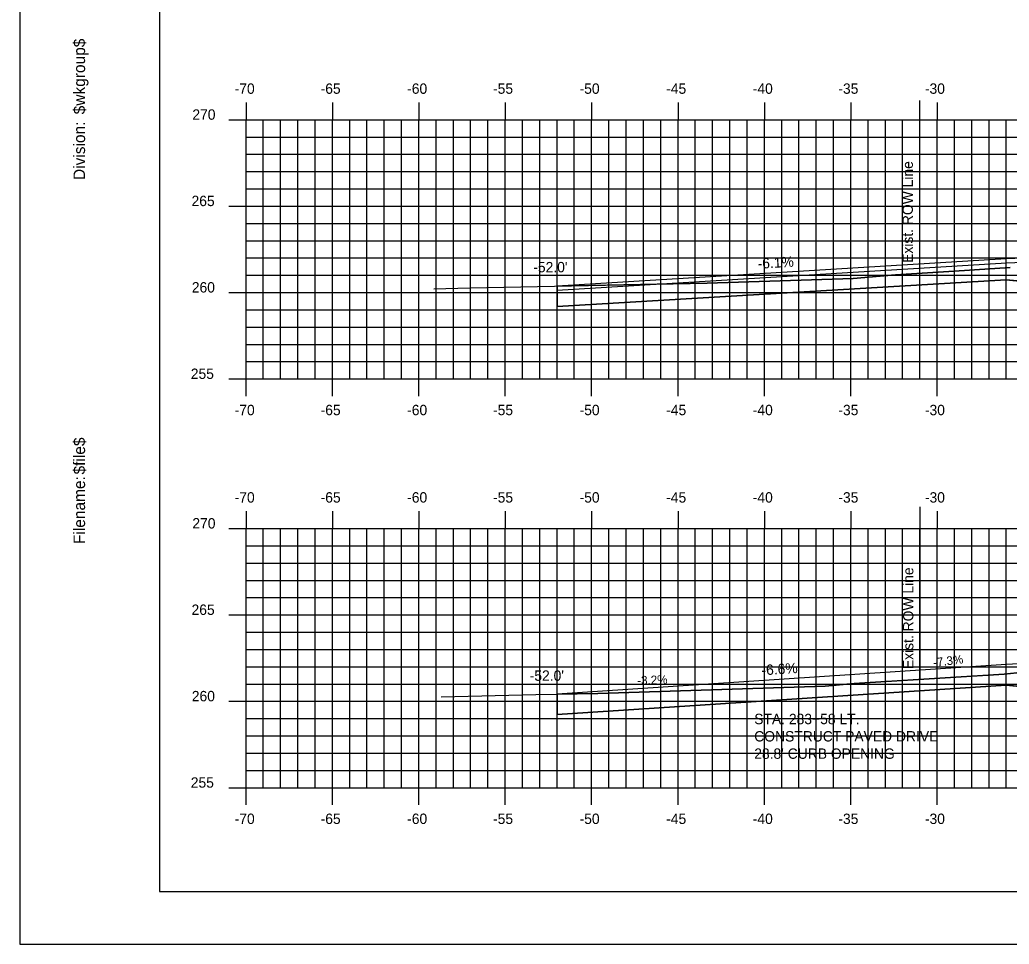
# Model space of a CAD drawing. Extents: x 856235 to 856405, y 366268 to 366378.
# Drawn here: x 856234.7 to 856291.9, y 366268.2 to 366321.7 of the extents above; entities that cross this region are included whole.
import ezdxf

# ---------------------------------------------------------------- set-up
doc = ezdxf.new("R2010")
doc.units = 0
for name, color, linetype in [('ANNOTATION', 7, 'Continuous'), ('BORDER', 7, 'Continuous'), ('D_Roadway_Drive_Gravel_LT', 7, 'Continuous'), ('D_Roadway_Drive_SubGrade', 7, 'Continuous'), ('D_Text_Monospaced', 7, 'Continuous'), ('D_Text_Standard', 7, 'Continuous'), ('E_ROW_Line', 7, 'Continuous'), ('H_V ANNOTATION', 7, 'Continuous'), ('JUNK COM EXC', 7, 'Continuous'), ('MAJOR', 7, 'Continuous'), ('MINOR', 7, 'Continuous'), ('PLOT BOUNDARY', 7, 'Continuous'), ('S_Roadway_Centerline', 7, 'Continuous')]:
    doc.layers.add(name, color=color, linetype=linetype)

msp = doc.modelspace()

# ---------------------------------------------------------------- linework, layer by layer
at = {"layer": 'BORDER'}
for p, q in [((856242.781, 366376.236), (856242.781, 366271.236)), ((856242.781, 366271.236), (856402.781, 366271.236))]:
    msp.add_line(p, q, dxfattribs=at)
at = {"layer": 'D_Roadway_Drive_Gravel_LT'}
for p, q in [((856291.781, 366307.834), (856265.781, 366306.26)), ((856291.796, 366307.584), (856265.781, 366306.009)), ((856297.781, 366308.074), (856291.781, 366307.834)), ((856297.791, 366307.824), (856291.791, 366307.584)), ((856291.781, 366306.632), (856265.781, 366305.093)), ((856291.781, 366284.374), (856265.781, 366282.647)), ((856297.781, 366284.614), (856291.781, 366284.374)), ((856291.781, 366283.178), (856265.781, 366281.48))]:
    msp.add_line(p, q, dxfattribs=at)
at = {"layer": 'D_Roadway_Drive_SubGrade'}
for p, q in [((856301.781, 366305.64), (856291.781, 366306.632)), ((856265.781, 366306.26), (856265.781, 366305.093)), ((856301.781, 366282.181), (856291.781, 366283.178)), ((856265.781, 366282.647), (856265.781, 366281.48))]:
    msp.add_line(p, q, dxfattribs=at)
at = {"layer": 'E_ROW_Line'}
for p, q in [((856286.774, 366307.01), (856286.774, 366317.01)), ((856286.803, 366283.499), (856286.803, 366293.499))]:
    msp.add_line(p, q, dxfattribs=at)
at = {"layer": 'JUNK COM EXC'}
for points in [[(856291.997, 366307.346), (856288.766, 366307.134), (856285.366, 366306.922), (856282.92, 366306.703), (856278.69, 366306.569), (856274.46, 366306.436), (856265.781, 366306.26), (856265.781, 366305.093), (856291.781, 366306.632), (856301.781, 366305.64)], [(856293.851, 366284.031), (856291.653, 366283.81), (856282.975, 366283.26), (856281.3, 366283.11), (856274.723, 366282.902), (856268.146, 366282.695), (856265.781, 366282.647), (856265.781, 366281.48), (856291.781, 366283.178), (856301.781, 366282.181)]]:
    msp.add_lwpolyline(points, dxfattribs=at)
at = {"layer": 'MAJOR'}
for p, q in [((856247.781, 366316.895), (856247.781, 366315.893)), ((856252.781, 366316.895), (856252.781, 366315.893)), ((856257.781, 366316.895), (856257.781, 366315.893)), ((856262.781, 366316.895), (856262.781, 366315.893)), ((856267.781, 366316.895), (856267.781, 366315.893)), ((856272.781, 366316.895), (856272.781, 366315.893)), ((856277.781, 366316.895), (856277.781, 366315.893)), ((856282.781, 366316.895), (856282.781, 366315.893)), ((856287.781, 366316.895), (856287.781, 366315.893)), ((856246.779, 366315.893), (856247.781, 366315.893)), ((856247.781, 366315.893), (856387.781, 366315.893)), ((856247.781, 366300.893), (856247.781, 366315.893)), ((856247.781, 366300.893), (856247.781, 366315.893)), ((856247.781, 366315.893), (856387.781, 366315.893)), ((856252.781, 366300.893), (856252.781, 366315.893)), ((856257.781, 366300.893), (856257.781, 366315.893)), ((856262.781, 366300.893), (856262.781, 366315.893)), ((856267.781, 366300.893), (856267.781, 366315.893)), ((856272.781, 366300.893), (856272.781, 366315.893)), ((856277.781, 366300.893), (856277.781, 366315.893)), ((856282.781, 366300.893), (856282.781, 366315.893)), ((856287.781, 366300.893), (856287.781, 366315.893)), ((856246.779, 366310.893), (856247.781, 366310.893)), ((856247.781, 366310.893), (856387.781, 366310.893)), ((856246.779, 366305.893), (856247.781, 366305.893)), ((856247.781, 366305.893), (856387.781, 366305.893)), ((856246.779, 366300.893), (856247.781, 366300.893)), ((856247.781, 366300.893), (856387.781, 366300.893)), ((856247.781, 366300.893), (856387.781, 366300.893)), ((856247.781, 366299.891), (856247.781, 366300.893)), ((856252.781, 366299.891), (856252.781, 366300.893)), ((856257.781, 366299.891), (856257.781, 366300.893)), ((856262.781, 366299.891), (856262.781, 366300.893)), ((856267.781, 366299.891), (856267.781, 366300.893)), ((856272.781, 366299.891), (856272.781, 366300.893)), ((856277.781, 366299.891), (856277.781, 366300.893)), ((856282.781, 366299.891), (856282.781, 366300.893)), ((856287.781, 366299.891), (856287.781, 366300.893)), ((856247.781, 366293.238), (856247.781, 366292.236)), ((856252.781, 366293.238), (856252.781, 366292.236)), ((856257.781, 366293.238), (856257.781, 366292.236)), ((856262.781, 366293.238), (856262.781, 366292.236)), ((856267.781, 366293.238), (856267.781, 366292.236)), ((856272.781, 366293.238), (856272.781, 366292.236)), ((856277.781, 366293.238), (856277.781, 366292.236)), ((856282.781, 366293.238), (856282.781, 366292.236)), ((856287.781, 366293.238), (856287.781, 366292.236)), ((856246.779, 366292.236), (856247.781, 366292.236)), ((856247.781, 366292.236), (856387.781, 366292.236)), ((856247.781, 366277.236), (856247.781, 366292.236)), ((856247.781, 366277.236), (856247.781, 366292.236)), ((856247.781, 366292.236), (856387.781, 366292.236)), ((856252.781, 366277.236), (856252.781, 366292.236)), ((856257.781, 366277.236), (856257.781, 366292.236)), ((856262.781, 366277.236), (856262.781, 366292.236)), ((856267.781, 366277.236), (856267.781, 366292.236)), ((856272.781, 366277.236), (856272.781, 366292.236)), ((856277.781, 366277.236), (856277.781, 366292.236)), ((856282.781, 366277.236), (856282.781, 366292.236)), ((856287.781, 366277.236), (856287.781, 366292.236)), ((856246.779, 366287.236), (856247.781, 366287.236)), ((856247.781, 366287.236), (856387.781, 366287.236)), ((856246.779, 366282.236), (856247.781, 366282.236)), ((856247.781, 366282.236), (856387.781, 366282.236)), ((856246.779, 366277.236), (856247.781, 366277.236)), ((856247.781, 366277.236), (856387.781, 366277.236)), ((856247.781, 366277.236), (856387.781, 366277.236)), ((856247.781, 366276.234), (856247.781, 366277.236)), ((856252.781, 366276.234), (856252.781, 366277.236)), ((856257.781, 366276.234), (856257.781, 366277.236)), ((856262.781, 366276.234), (856262.781, 366277.236)), ((856267.781, 366276.234), (856267.781, 366277.236)), ((856272.781, 366276.234), (856272.781, 366277.236)), ((856277.781, 366276.234), (856277.781, 366277.236)), ((856282.781, 366276.234), (856282.781, 366277.236)), ((856287.781, 366276.234), (856287.781, 366277.236))]:
    msp.add_line(p, q, dxfattribs=at)
at = {"layer": 'MINOR'}
for p, q in [((856248.781, 366300.893), (856248.781, 366315.893)), ((856249.781, 366300.893), (856249.781, 366315.893)), ((856250.781, 366300.893), (856250.781, 366315.893)), ((856251.781, 366300.893), (856251.781, 366315.893)), ((856253.781, 366300.893), (856253.781, 366315.893)), ((856254.781, 366300.893), (856254.781, 366315.893)), ((856255.781, 366300.893), (856255.781, 366315.893)), ((856256.781, 366300.893), (856256.781, 366315.893)), ((856258.781, 366300.893), (856258.781, 366315.893)), ((856259.781, 366300.893), (856259.781, 366315.893)), ((856260.781, 366300.893), (856260.781, 366315.893)), ((856261.781, 366300.893), (856261.781, 366315.893)), ((856263.781, 366300.893), (856263.781, 366315.893)), ((856264.781, 366300.893), (856264.781, 366315.893)), ((856265.781, 366300.893), (856265.781, 366315.893)), ((856266.781, 366300.893), (856266.781, 366315.893)), ((856268.781, 366300.893), (856268.781, 366315.893)), ((856269.781, 366300.893), (856269.781, 366315.893)), ((856270.781, 366300.893), (856270.781, 366315.893)), ((856271.781, 366300.893), (856271.781, 366315.893)), ((856273.781, 366300.893), (856273.781, 366315.893)), ((856274.781, 366300.893), (856274.781, 366315.893)), ((856275.781, 366300.893), (856275.781, 366315.893)), ((856276.781, 366300.893), (856276.781, 366315.893)), ((856278.781, 366300.893), (856278.781, 366315.893)), ((856279.781, 366300.893), (856279.781, 366315.893)), ((856280.781, 366300.893), (856280.781, 366315.893)), ((856281.781, 366300.893), (856281.781, 366315.893)), ((856283.781, 366300.893), (856283.781, 366315.893)), ((856284.781, 366300.893), (856284.781, 366315.893)), ((856285.781, 366300.893), (856285.781, 366315.893)), ((856286.781, 366300.893), (856286.781, 366315.893)), ((856288.781, 366300.893), (856288.781, 366315.893)), ((856289.781, 366300.893), (856289.781, 366315.893)), ((856290.781, 366300.893), (856290.781, 366315.893)), ((856291.781, 366300.893), (856291.781, 366315.893)), ((856247.781, 366314.893), (856387.781, 366314.893)), ((856247.781, 366314.893), (856248.783, 366314.893)), ((856247.781, 366313.893), (856387.781, 366313.893)), ((856247.781, 366313.893), (856248.783, 366313.893)), ((856247.781, 366312.893), (856387.781, 366312.893)), ((856247.781, 366312.893), (856248.783, 366312.893)), ((856247.781, 366311.893), (856387.781, 366311.893)), ((856247.781, 366311.893), (856248.783, 366311.893)), ((856247.781, 366309.893), (856387.781, 366309.893)), ((856247.781, 366309.893), (856248.783, 366309.893)), ((856247.781, 366308.893), (856387.781, 366308.893)), ((856247.781, 366308.893), (856248.783, 366308.893)), ((856247.781, 366307.893), (856387.781, 366307.893)), ((856247.781, 366307.893), (856248.783, 366307.893)), ((856247.781, 366306.893), (856387.781, 366306.893)), ((856247.781, 366306.893), (856248.783, 366306.893)), ((856247.781, 366304.893), (856387.781, 366304.893)), ((856247.781, 366304.893), (856248.783, 366304.893)), ((856247.781, 366303.893), (856387.781, 366303.893)), ((856247.781, 366303.893), (856248.783, 366303.893)), ((856247.781, 366302.893), (856387.781, 366302.893)), ((856247.781, 366302.893), (856248.783, 366302.893)), ((856247.781, 366301.893), (856387.781, 366301.893)), ((856247.781, 366301.893), (856248.783, 366301.893)), ((856248.781, 366277.236), (856248.781, 366292.236)), ((856249.781, 366277.236), (856249.781, 366292.236)), ((856250.781, 366277.236), (856250.781, 366292.236)), ((856251.781, 366277.236), (856251.781, 366292.236)), ((856253.781, 366277.236), (856253.781, 366292.236)), ((856254.781, 366277.236), (856254.781, 366292.236)), ((856255.781, 366277.236), (856255.781, 366292.236)), ((856256.781, 366277.236), (856256.781, 366292.236)), ((856258.781, 366277.236), (856258.781, 366292.236)), ((856259.781, 366277.236), (856259.781, 366292.236)), ((856260.781, 366277.236), (856260.781, 366292.236)), ((856261.781, 366277.236), (856261.781, 366292.236)), ((856263.781, 366277.236), (856263.781, 366292.236)), ((856264.781, 366277.236), (856264.781, 366292.236)), ((856265.781, 366277.236), (856265.781, 366292.236)), ((856266.781, 366277.236), (856266.781, 366292.236)), ((856268.781, 366277.236), (856268.781, 366292.236)), ((856269.781, 366277.236), (856269.781, 366292.236)), ((856270.781, 366277.236), (856270.781, 366292.236)), ((856271.781, 366277.236), (856271.781, 366292.236)), ((856273.781, 366277.236), (856273.781, 366292.236)), ((856274.781, 366277.236), (856274.781, 366292.236)), ((856275.781, 366277.236), (856275.781, 366292.236)), ((856276.781, 366277.236), (856276.781, 366292.236)), ((856278.781, 366277.236), (856278.781, 366292.236)), ((856279.781, 366277.236), (856279.781, 366292.236)), ((856280.781, 366277.236), (856280.781, 366292.236)), ((856281.781, 366277.236), (856281.781, 366292.236)), ((856283.781, 366277.236), (856283.781, 366292.236)), ((856284.781, 366277.236), (856284.781, 366292.236)), ((856285.781, 366277.236), (856285.781, 366292.236)), ((856286.781, 366277.236), (856286.781, 366292.236)), ((856288.781, 366277.236), (856288.781, 366292.236)), ((856289.781, 366277.236), (856289.781, 366292.236)), ((856290.781, 366277.236), (856290.781, 366292.236)), ((856291.781, 366277.236), (856291.781, 366292.236)), ((856247.781, 366291.236), (856387.781, 366291.236)), ((856247.781, 366291.236), (856248.783, 366291.236)), ((856247.781, 366290.236), (856387.781, 366290.236)), ((856247.781, 366290.236), (856248.783, 366290.236)), ((856247.781, 366289.236), (856387.781, 366289.236)), ((856247.781, 366289.236), (856248.783, 366289.236)), ((856247.781, 366288.236), (856387.781, 366288.236)), ((856247.781, 366288.236), (856248.783, 366288.236)), ((856247.781, 366286.236), (856387.781, 366286.236)), ((856247.781, 366286.236), (856248.783, 366286.236)), ((856247.781, 366285.236), (856387.781, 366285.236)), ((856247.781, 366285.236), (856248.783, 366285.236)), ((856247.781, 366284.236), (856387.781, 366284.236)), ((856247.781, 366284.236), (856248.783, 366284.236)), ((856247.781, 366283.236), (856387.781, 366283.236)), ((856247.781, 366283.236), (856248.783, 366283.236)), ((856247.781, 366281.236), (856387.781, 366281.236)), ((856247.781, 366281.236), (856248.783, 366281.236)), ((856247.781, 366280.236), (856387.781, 366280.236)), ((856247.781, 366280.236), (856248.783, 366280.236)), ((856247.781, 366279.236), (856387.781, 366279.236)), ((856247.781, 366279.236), (856248.783, 366279.236)), ((856247.781, 366278.236), (856387.781, 366278.236)), ((856247.781, 366278.236), (856248.783, 366278.236))]:
    msp.add_line(p, q, dxfattribs=at)
at = {"layer": 'PLOT BOUNDARY'}
msp.add_lwpolyline([(856234.688, 366268.177), (856404.688, 366268.177), (856404.688, 366378.177), (856234.688, 366378.177)], close=True, dxfattribs=at)
at = {"layer": 'S_Roadway_Centerline'}
for points in [[(856258.655, 366306.107), (856260.727, 366306.157), (856274.46, 366306.436), (856282.92, 366306.703), (856285.366, 366306.922), (856288.766, 366307.134), (856291.997, 366307.346)], [(856259.077, 366282.489), (856264.552, 366282.622), (856268.146, 366282.695), (856281.3, 366283.11), (856282.975, 366283.26), (856289.167, 366283.647), (856291.653, 366283.81), (856293.851, 366284.031)]]:
    msp.add_lwpolyline(points, dxfattribs=at)

# ---------------------------------------------------------------- texts
at = {"layer": 'ANNOTATION'}
for s, p in [('STA. 283+58 LT.', (856277.193, 366280.911)), ('CONSTRUCT PAVED DRIVE', (856277.193, 366279.909)), ("28.8' CURB OPENING", (856277.193, 366278.907))]:
    msp.add_text(s, height=0.6, dxfattribs=at).set_placement(p)
at = {"layer": 'BORDER'}
for s, p in [('$wkgroup$', (856238.466, 366316.206)), ('Division:', (856238.466, 366312.403)), ('$file$', (856238.466, 366295.362)), ('Filename:', (856238.466, 366291.335))]:
    msp.add_text(s, height=0.6696, rotation=90, dxfattribs=at).set_placement(p)
at = {"layer": 'D_Text_Monospaced'}
for s, rotation, p in [('-7.3%', 7.0925, (856287.578, 366284.222)), ('-3.2%', 1.9543, (856270.43, 366283.19))]:
    msp.add_text(s, height=0.5, rotation=rotation, dxfattribs=at).set_placement(p)
at = {"layer": 'D_Text_Standard'}
for p in [(856264.406, 366307.062), (856264.198, 366283.422)]:
    msp.add_text("-52.0'", height=0.6, dxfattribs=at).set_placement(p)
for s, rotation, p in [('-6.1%', 3.4652, (856277.405, 366307.264)), ('-6.6%', 3.8015, (856277.629, 366283.735))]:
    msp.add_text(s, height=0.6, rotation=rotation, dxfattribs=at).set_placement(p)
at = {"layer": 'E_ROW_Line'}
for p in [(856286.374, 366307.61), (856286.403, 366284.099)]:
    msp.add_text('Exist. ROW Line', height=0.6, rotation=90, dxfattribs=at).set_placement(p)
at = {"layer": 'H_V ANNOTATION'}
for s, p in [('-70', (856247.122, 366317.393)), ('-65', (856252.098, 366317.393)), ('-60', (856257.106, 366317.393)), ('-55', (856262.077, 366317.393)), ('-50', (856267.085, 366317.393)), ('-45', (856272.098, 366317.393)), ('-40', (856277.106, 366317.393)), ('-35', (856282.061, 366317.393)), ('-30', (856287.069, 366317.393)), ('270', (856244.675, 366315.893)), ('265', (856244.627, 366310.893)), ('260', (856244.643, 366305.893)), ('255', (856244.584, 366300.893)), ('-70', (856247.122, 366298.793)), ('-65', (856252.098, 366298.793)), ('-60', (856257.106, 366298.793)), ('-55', (856262.077, 366298.793)), ('-50', (856267.085, 366298.793)), ('-45', (856272.098, 366298.793)), ('-40', (856277.106, 366298.793)), ('-35', (856282.061, 366298.793)), ('-30', (856287.069, 366298.793)), ('-70', (856247.122, 366293.736)), ('-65', (856252.098, 366293.736)), ('-60', (856257.106, 366293.736)), ('-55', (856262.077, 366293.736)), ('-50', (856267.085, 366293.736)), ('-45', (856272.098, 366293.736)), ('-40', (856277.106, 366293.736)), ('-35', (856282.061, 366293.736)), ('-30', (856287.069, 366293.736)), ('270', (856244.675, 366292.236)), ('265', (856244.627, 366287.236)), ('260', (856244.643, 366282.236)), ('255', (856244.584, 366277.236)), ('-70', (856247.122, 366275.136)), ('-65', (856252.098, 366275.136)), ('-60', (856257.106, 366275.136)), ('-55', (856262.077, 366275.136)), ('-50', (856267.085, 366275.136)), ('-45', (856272.098, 366275.136)), ('-40', (856277.106, 366275.136)), ('-35', (856282.061, 366275.136)), ('-30', (856287.069, 366275.136))]:
    msp.add_text(s, height=0.6, dxfattribs=at).set_placement(p)
at = {"layer": 'MAJOR'}
for p in [(856247.776, 366300.893), (856247.776, 366277.236)]:
    msp.add_text('-', height=0.00000006, rotation=53.1301, dxfattribs=at).set_placement(p)

doc.saveas('drawing.dxf')
